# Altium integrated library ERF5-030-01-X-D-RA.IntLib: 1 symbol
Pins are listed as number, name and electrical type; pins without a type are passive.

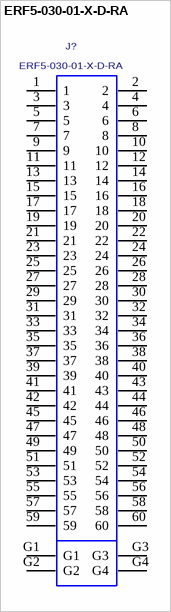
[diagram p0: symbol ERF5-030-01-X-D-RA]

## ERF5-030-01-X-D-RA
designator J?
0.5mm Right Angle Socket Assembly, 60 Pins.; MANUFACTURER: SAMTEC
footprint ERF5-030-01-X-D-RA
pins: 1, 2, 3, 4, 5, 6, 7, 8, 9, 10, 11, 12, 13, 14, 15, 16, 17, 18, 19, 20, 21, 22, 23, 24, 25, 26, 27, 28, 29, 30, 31, 32, 33, 34, 35, 36, 37, 38, 39, 40, 41, 42, 43, 44, 45, 46, 47, 48, 49, 50, 51, 52, 53, 54, 55, 56, 57, 58, 59, 60, G1, G2, G3, G4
